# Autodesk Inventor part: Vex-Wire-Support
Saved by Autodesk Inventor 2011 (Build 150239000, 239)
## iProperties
Created: 2007-08
Part Number: Vex-Wire-Support
Document SubType Name: Modeling
Density: 1 g/cm^3
Mass: 0.120142 g
Surface Area: 2.78928 cm^2
Volume: 0.120142 cm^3
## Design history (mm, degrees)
feature "Base1"
body "Solid1"
